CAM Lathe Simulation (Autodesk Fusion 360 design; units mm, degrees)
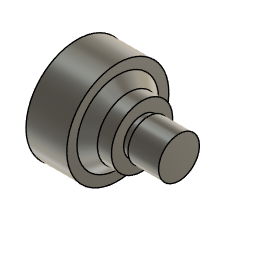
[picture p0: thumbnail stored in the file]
sketch "Sketch1" plane through (0, 0, 0) normal (0, 1, 0) x axis (1, 0, 0)
  line L1 (63.5, 0) -> (0, 0)
  line L2 (38.1, 0) -> (0, 0)
  line L3 (38.1, -6.35) -> (38.1, 0)
  line L4 (60.325, -6.35) -> (38.1, -6.35)
  line L5 (63.5, -9.525) -> (60.325, -6.35)
  line L6 (63.5, -12.7) -> (63.5, -9.525)
  line L7 (44.45, -12.7) -> (63.5, -12.7)
  line L8 (44.45, -11.43) -> (44.45, -12.7)
  line L9 (40.4812, -11.43) -> (44.45, -11.43)
  line L10 (40.4812, -19.05) -> (40.4812, -11.43)
  line L11 (31.75, -19.05) -> (40.4812, -19.05)
  line L12 (25.4, -25.4) -> (31.75, -19.05)
  line L13 (25.4, -31.75) -> (25.4, -25.4)
  line L14 (0, -31.75) -> (25.4, -31.75)
  line L15 (0, 0) -> (0, -31.75)
  line L16 (63.5, 0) -> (63.5, -9.525)
  point P1 (0, 0)
  point P2 (0, 0)
  point P4 (0, 0)
  point P5 (38.1, 0)
  point P18 (0, 0)
  point P3 (63.5, 0)
  point P7 (60.325, -6.35)
  point P8 (63.5, -9.525)
  point P10 (44.45, -12.7)
  point P11 (44.45, -11.43)
  point P9 (63.5, -12.7)
  point P14 (31.75, -19.05)
  point P15 (25.4, -25.4)
  point P16 (25.4, -31.75)
  point P17 (0, -31.75)
  coincident P1 P2
  horizontal L1
  coincident P1 P4
  coincident L1 P5
  parallel L1 L2
  perpendicular L2 L3
  perpendicular L3 L4
  perpendicular L4 L6
  perpendicular L6 L7
  perpendicular L7 L8
  perpendicular L8 L9
  perpendicular L9 L10
  perpendicular L10 L11
  perpendicular L11 L13
  perpendicular L13 L14
  coincident P1 P18
  perpendicular L1 L15
  coincident P3 L6
  dimension "d1" distance P2 P3 = 63.5
  dimension "d2" angle L4 L5 = 45
  dimension "d3" distance P7 P8 = 3.175
  dimension "d4" = 12.7
  dimension "d5" distance L3 L6 = 25.4
  dimension "d7" distance L8 L10 = 3.9688
  dimension "d8" distance P10 P11 = 1.27
  dimension "d9" distance P9 P10 = 19.05
  dimension "d10" angle L11 L12 = 45
  dimension "d11" distance P14 P15 = 6.35
  dimension "d12" = 63.5
  dimension "d13" distance P16 P17 = 25.4
  dimension "d15" = 25.4
  dimension "d16" = 38.1
revolve "Revolve1" sketch "Sketch1" AlongAngle 360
